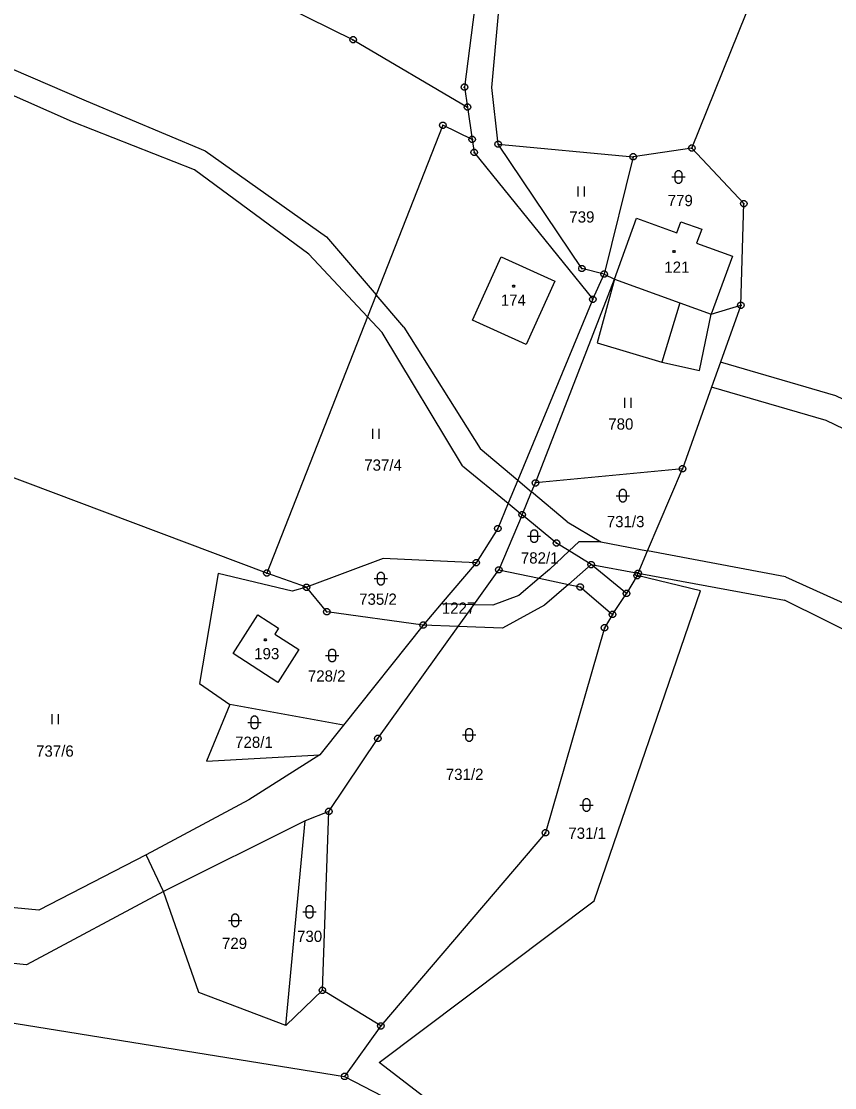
# Model space of a CAD drawing. Extents: x -694465 to -690527, y -983694 to -978978.
# Drawn here: x -690934.9 to -690812.1, y -980605.1 to -980444.1 of the extents above; entities that cross this region are included whole.
import ezdxf

# ---------------------------------------------------------------- set-up
doc = ezdxf.new("R2010")
doc.units = 0
for name, color, linetype in [('Vrstva 1', 7, 'Continuous'), ('Vrstva 18', 7, 'Continuous'), ('Vrstva 19', 7, 'Continuous'), ('Vrstva 24', 7, 'Continuous'), ('Vrstva 25', 7, 'Continuous')]:
    doc.layers.add(name, color=color, linetype=linetype)

msp = doc.modelspace()

# ---------------------------------------------------------------- linework, layer by layer
at = {"layer": 'Vrstva 1'}
for points in [[(-690865.21, -980431.98), (-690868.03, -980454.02)], [(-690863.87, -980454.07), (-690861.93, -980432.34)], [(-690895.13, -980441.8), (-690884.84, -980446.86)], [(-690833.66, -980463.22), (-690825.488, -980442.912)], [(-690884.84, -980446.86), (-690867.57, -980457.03)], [(-690936.46, -980451.23), (-690925.16, -980456.08)], [(-690927.2, -980459.26), (-690937.78, -980454.57)], [(-690868.03, -980454.02), (-690867.57, -980457.03)], [(-690862.93, -980462.64), (-690863.87, -980454.07)], [(-690925.16, -980456.08), (-690907.17, -980463.65)], [(-690867.57, -980457.03), (-690866.84, -980461.91)], [(-690908.81, -980466.51), (-690927.2, -980459.26)], [(-690871.29, -980459.78), (-690881.35, -980485.41)], [(-690866.84, -980461.91), (-690871.29, -980459.78)], [(-690866.84, -980461.91), (-690866.54, -980463.88)], [(-690907.17, -980463.65), (-690888.85, -980476.65)], [(-690850.27, -980481.42), (-690862.93, -980462.64)], [(-690862.93, -980462.64), (-690842.56, -980464.55)], [(-690833.66, -980463.22), (-690842.56, -980464.55)], [(-690825.84, -980471.62), (-690833.66, -980463.22)], [(-690866.54, -980463.88), (-690848.65, -980486.07)], [(-690842.56, -980464.55), (-690846.92, -980482.26)], [(-690891.52, -980479.26), (-690908.81, -980466.51)], [(-690826.26, -980486.97), (-690825.84, -980471.62)], [(-690845.37, -980483.01), (-690842.02, -980473.81)], [(-690842.02, -980473.81), (-690835.94, -980476.02)], [(-690835.94, -980476.02), (-690835.33, -980474.36)], [(-690835.33, -980474.36), (-690832.19, -980475.5)], [(-690832.19, -980475.5), (-690832.95, -980477.6)], [(-690888.85, -980476.65), (-690881.35, -980485.41)], [(-690832.95, -980477.6), (-690827.55, -980479.57)], [(-690891.52, -980479.26), (-690882.65, -980488.72)], [(-690854.36, -980483.34), (-690858.69, -980492.92), (-690866.82, -980489.24), (-690862.49, -980479.67), (-690854.36, -980483.34)], [(-690827.55, -980479.57), (-690830.75, -980488.34)], [(-690846.92, -980482.26), (-690850.27, -980481.42)], [(-690848.65, -980486.07), (-690846.92, -980482.26)], [(-690846.92, -980482.26), (-690845.37, -980483.01)], [(-690857.3, -980513.8), (-690845.37, -980483.01)], [(-690845.37, -980483.01), (-690847.98, -980492.63)], [(-690845.37, -980483.01), (-690835.5, -980486.6)], [(-690881.35, -980485.41), (-690882.65, -980488.72)], [(-690877.17, -980490.3), (-690881.35, -980485.41)], [(-690848.65, -980486.07), (-690859.95, -980513.39)], [(-690835.5, -980486.6), (-690838.2, -980495.55)], [(-690835.5, -980486.6), (-690830.75, -980488.34)], [(-690830.75, -980488.34), (-690826.26, -980486.97)], [(-690826.26, -980486.97), (-690829.339, -980495.559)], [(-690882.65, -980488.72), (-690897.85, -980527.41)], [(-690880.46, -980491.06), (-690882.65, -980488.72)], [(-690832.54, -980496.81), (-690830.75, -980488.34)], [(-690877.17, -980490.3), (-690865.63, -980508.59)], [(-690868.3, -980511.2), (-690880.46, -980491.06)], [(-690847.98, -980492.63), (-690838.2, -980495.55)], [(-690838.2, -980495.55), (-690832.54, -980496.81)], [(-690829.339, -980495.559), (-690830.692, -980499.335)], [(-690686.191, -980555.869), (-690699.761, -980553.812), (-690734.587, -980544.354), (-690762.898, -980529.445), (-690786.026, -980513.096), (-690811.934, -980500.644), (-690829.339, -980495.559)], [(-690830.692, -980499.335), (-690835.11, -980511.66)], [(-690700.76, -980557.694), (-690736.061, -980548.098), (-690764.994, -980532.863), (-690788.062, -980516.556), (-690813.374, -980504.39), (-690830.692, -980499.335)], [(-690865.63, -980508.59), (-690859.95, -980513.39)], [(-690868.3, -980511.2), (-690861.4, -980516.88)], [(-690835.11, -980511.66), (-690857.3, -980513.8)], [(-690840.35, -980524.05), (-690835.11, -980511.66)], [(-690897.85, -980527.41), (-690938.29, -980512.22)], [(-690859.95, -980513.39), (-690861.4, -980516.88)], [(-690859.95, -980513.39), (-690857.87, -980515.15)], [(-690859.31, -980518.6), (-690857.87, -980515.15)], [(-690857.87, -980515.15), (-690857.3, -980513.8)], [(-690852.49, -980519.7), (-690857.87, -980515.15)], [(-690861.4, -980516.88), (-690862.98, -980520.69)], [(-690861.4, -980516.88), (-690859.31, -980518.6)], [(-690859.31, -980518.6), (-690862.81, -980526.93)], [(-690854.12, -980522.88), (-690859.31, -980518.6)], [(-690852.49, -980519.7), (-690847.4, -980522.71)], [(-690862.98, -980520.69), (-690866.24, -980525.85)], [(-690852.194, -980524.078), (-690854.12, -980522.88)], [(-690847.4, -980522.71), (-690850.763, -980522.725), (-690852.194, -980524.078)], [(-690847.4, -980522.71), (-690840.35, -980524.05)], [(-690852.194, -980524.078), (-690855.173, -980526.893), (-690856.732, -980528.207)], [(-690848.88, -980526.14), (-690852.194, -980524.078)], [(-690841.79, -980527.44), (-690840.35, -980524.05)], [(-690819.55, -980527.99), (-690840.35, -980524.05)], [(-690880.31, -980525.21), (-690891.88, -980529.56)], [(-690866.24, -980525.85), (-690880.31, -980525.21)], [(-690866.24, -980525.85), (-690871.555, -980532.091)], [(-690848.88, -980526.14), (-690852.307, -980529.137)], [(-690843.56, -980530.49), (-690848.88, -980526.14)], [(-690848.88, -980526.14), (-690841.79, -980527.44)], [(-690905.21, -980527.48), (-690908.04, -980544.08)], [(-690894.04, -980530.17), (-690905.21, -980527.48)], [(-690891.88, -980529.56), (-690897.85, -980527.41)], [(-690866.609, -980532.215), (-690862.81, -980526.93)], [(-690862.81, -980526.93), (-690856.732, -980528.207)], [(-690841.94, -980527.81), (-690843.56, -980530.49)], [(-690841.94, -980527.81), (-690841.79, -980527.44)], [(-690832.37, -980530.09), (-690841.94, -980527.81)], [(-690841.79, -980527.44), (-690819.67, -980531.51)], [(-690819.55, -980527.99), (-690799.34, -980537.1)], [(-690891.88, -980529.56), (-690894.04, -980530.17)], [(-690888.8, -980533.27), (-690891.88, -980529.56)], [(-690852.307, -980529.137), (-690855.909, -980532.287), (-690862.28, -980535.719), (-690868.952, -980535.475)], [(-690856.732, -980528.207), (-690859.829, -980530.816), (-690863.75, -980532.287), (-690866.609, -980532.215)], [(-690856.732, -980528.207), (-690852.307, -980529.137)], [(-690852.307, -980529.137), (-690850.53, -980529.51)], [(-690850.53, -980529.51), (-690845.65, -980533.66)], [(-690848.44, -980576.92), (-690832.37, -980530.09)], [(-690845.65, -980533.66), (-690843.56, -980530.49)], [(-690871.555, -980532.091), (-690874.27, -980535.28)], [(-690866.609, -980532.215), (-690871.555, -980532.091)], [(-690868.952, -980535.475), (-690866.609, -980532.215)], [(-690801.3, -980540.6), (-690819.67, -980531.51)], [(-690893.02, -980538.98), (-690896.22, -980543.93), (-690902.96, -980539.57), (-690899.2, -980533.73), (-690896.1, -980535.73), (-690896.67, -980536.63), (-690893.02, -980538.98)], [(-690874.27, -980535.28), (-690888.8, -980533.27)], [(-690845.65, -980533.66), (-690846.85, -980535.68)], [(-690874.27, -980535.28), (-690886.28, -980550.41)], [(-690881.11, -980552.39), (-690868.952, -980535.475)], [(-690868.952, -980535.475), (-690874.27, -980535.28)], [(-690846.85, -980535.68), (-690855.8, -980566.65)], [(-690908.04, -980544.08), (-690903.44, -980547.26)], [(-690903.44, -980547.26), (-690906.98, -980555.85)], [(-690886.28, -980550.41), (-690903.44, -980547.26)], [(-690886.28, -980550.41), (-690889.85, -980554.85)], [(-690888.52, -980563.42), (-690881.11, -980552.39)], [(-690906.98, -980555.85), (-690889.85, -980554.85)], [(-690889.85, -980554.85), (-690900.57, -980561.68)], [(-690900.57, -980561.68), (-690916.11, -980569.98)], [(-690888.52, -980563.42), (-690892.05, -980564.82)], [(-690889.48, -980590.44), (-690888.52, -980563.42)], [(-690892.05, -980564.82), (-690913.45, -980575.53)], [(-690894.98, -980595.74), (-690892.05, -980564.82)], [(-690855.8, -980566.65), (-690880.66, -980595.82)], [(-690916.11, -980569.98), (-690932.28, -980578.35)], [(-690913.45, -980575.53), (-690916.11, -980569.98)], [(-690932.28, -980578.35), (-690960.27, -980575.64)], [(-690913.45, -980575.53), (-690934.14, -980586.57)], [(-690908.12, -980590.79), (-690913.45, -980575.53)], [(-690880.89, -980601.34), (-690848.44, -980576.92)], [(-690934.14, -980586.57), (-691001.09, -980579.72)], [(-691001.55, -980584.83), (-690886.11, -980603.44)], [(-690894.98, -980595.74), (-690908.12, -980590.79)], [(-690889.48, -980590.44), (-690894.98, -980595.74)], [(-690880.66, -980595.82), (-690889.48, -980590.44)], [(-690880.66, -980595.82), (-690886.11, -980603.44)], [(-690861.7, -980616.11), (-690880.89, -980601.34)], [(-690886.11, -980603.44), (-690861.7, -980616.11)]]:
    msp.add_lwpolyline(points, dxfattribs=at)
at = {"layer": 'Vrstva 24'}
for points in [[(-690884.686, -980446.384), (-690884.436, -980446.566), (-690884.34, -980446.86), (-690884.436, -980447.154), (-690884.686, -980447.336), (-690884.994, -980447.336), (-690885.244, -980447.154), (-690885.34, -980446.86), (-690885.244, -980446.566), (-690884.994, -980446.384)], [(-690867.876, -980453.544), (-690867.626, -980453.726), (-690867.53, -980454.02), (-690867.626, -980454.314), (-690867.876, -980454.496), (-690868.184, -980454.496), (-690868.434, -980454.314), (-690868.53, -980454.02), (-690868.434, -980453.726), (-690868.184, -980453.544)], [(-690867.416, -980456.554), (-690867.166, -980456.736), (-690867.07, -980457.03), (-690867.166, -980457.324), (-690867.416, -980457.506), (-690867.724, -980457.506), (-690867.974, -980457.324), (-690868.07, -980457.03), (-690867.974, -980456.736), (-690867.724, -980456.554)], [(-690871.136, -980459.304), (-690870.886, -980459.486), (-690870.79, -980459.78), (-690870.886, -980460.074), (-690871.136, -980460.256), (-690871.444, -980460.256), (-690871.694, -980460.074), (-690871.79, -980459.78), (-690871.694, -980459.486), (-690871.444, -980459.304)], [(-690866.686, -980461.434), (-690866.436, -980461.616), (-690866.34, -980461.91), (-690866.436, -980462.204), (-690866.686, -980462.386), (-690866.994, -980462.386), (-690867.244, -980462.204), (-690867.34, -980461.91), (-690867.244, -980461.616), (-690866.994, -980461.434)], [(-690866.386, -980463.404), (-690866.136, -980463.586), (-690866.04, -980463.88), (-690866.136, -980464.174), (-690866.386, -980464.356), (-690866.694, -980464.356), (-690866.944, -980464.174), (-690867.04, -980463.88), (-690866.944, -980463.586), (-690866.694, -980463.404)], [(-690862.776, -980462.164), (-690862.526, -980462.346), (-690862.43, -980462.64), (-690862.526, -980462.934), (-690862.776, -980463.116), (-690863.084, -980463.116), (-690863.334, -980462.934), (-690863.43, -980462.64), (-690863.334, -980462.346), (-690863.084, -980462.164)], [(-690833.506, -980462.744), (-690833.256, -980462.926), (-690833.16, -980463.22), (-690833.256, -980463.514), (-690833.506, -980463.696), (-690833.814, -980463.696), (-690834.064, -980463.514), (-690834.16, -980463.22), (-690834.064, -980462.926), (-690833.814, -980462.744)], [(-690842.406, -980464.074), (-690842.156, -980464.256), (-690842.06, -980464.55), (-690842.156, -980464.844), (-690842.406, -980465.026), (-690842.714, -980465.026), (-690842.964, -980464.844), (-690843.06, -980464.55), (-690842.964, -980464.256), (-690842.714, -980464.074)], [(-690825.686, -980471.144), (-690825.436, -980471.326), (-690825.34, -980471.62), (-690825.436, -980471.914), (-690825.686, -980472.096), (-690825.994, -980472.096), (-690826.244, -980471.914), (-690826.34, -980471.62), (-690826.244, -980471.326), (-690825.994, -980471.144)], [(-690850.116, -980480.944), (-690849.866, -980481.126), (-690849.77, -980481.42), (-690849.866, -980481.714), (-690850.116, -980481.896), (-690850.424, -980481.896), (-690850.674, -980481.714), (-690850.77, -980481.42), (-690850.674, -980481.126), (-690850.424, -980480.944)], [(-690846.766, -980481.784), (-690846.516, -980481.966), (-690846.42, -980482.26), (-690846.516, -980482.554), (-690846.766, -980482.736), (-690847.074, -980482.736), (-690847.324, -980482.554), (-690847.42, -980482.26), (-690847.324, -980481.966), (-690847.074, -980481.784)], [(-690848.496, -980485.594), (-690848.246, -980485.776), (-690848.15, -980486.07), (-690848.246, -980486.364), (-690848.496, -980486.546), (-690848.804, -980486.546), (-690849.054, -980486.364), (-690849.15, -980486.07), (-690849.054, -980485.776), (-690848.804, -980485.594)], [(-690826.106, -980486.494), (-690825.856, -980486.676), (-690825.76, -980486.97), (-690825.856, -980487.264), (-690826.106, -980487.446), (-690826.414, -980487.446), (-690826.664, -980487.264), (-690826.76, -980486.97), (-690826.664, -980486.676), (-690826.414, -980486.494)], [(-690834.956, -980511.184), (-690834.706, -980511.366), (-690834.61, -980511.66), (-690834.706, -980511.954), (-690834.956, -980512.136), (-690835.264, -980512.136), (-690835.514, -980511.954), (-690835.61, -980511.66), (-690835.514, -980511.366), (-690835.264, -980511.184)], [(-690857.146, -980513.324), (-690856.896, -980513.506), (-690856.8, -980513.8), (-690856.896, -980514.094), (-690857.146, -980514.276), (-690857.454, -980514.276), (-690857.704, -980514.094), (-690857.8, -980513.8), (-690857.704, -980513.506), (-690857.454, -980513.324)], [(-690859.156, -980518.124), (-690858.906, -980518.306), (-690858.81, -980518.6), (-690858.906, -980518.894), (-690859.156, -980519.076), (-690859.464, -980519.076), (-690859.714, -980518.894), (-690859.81, -980518.6), (-690859.714, -980518.306), (-690859.464, -980518.124)], [(-690862.826, -980520.214), (-690862.576, -980520.396), (-690862.48, -980520.69), (-690862.576, -980520.984), (-690862.826, -980521.166), (-690863.134, -980521.166), (-690863.384, -980520.984), (-690863.48, -980520.69), (-690863.384, -980520.396), (-690863.134, -980520.214)], [(-690853.966, -980522.404), (-690853.716, -980522.586), (-690853.62, -980522.88), (-690853.716, -980523.174), (-690853.966, -980523.356), (-690854.274, -980523.356), (-690854.524, -980523.174), (-690854.62, -980522.88), (-690854.524, -980522.586), (-690854.274, -980522.404)], [(-690866.086, -980525.374), (-690865.836, -980525.556), (-690865.74, -980525.85), (-690865.836, -980526.144), (-690866.086, -980526.326), (-690866.394, -980526.326), (-690866.644, -980526.144), (-690866.74, -980525.85), (-690866.644, -980525.556), (-690866.394, -980525.374)], [(-690862.656, -980526.454), (-690862.406, -980526.636), (-690862.31, -980526.93), (-690862.406, -980527.224), (-690862.656, -980527.406), (-690862.964, -980527.406), (-690863.214, -980527.224), (-690863.31, -980526.93), (-690863.214, -980526.636), (-690862.964, -980526.454)], [(-690848.726, -980525.664), (-690848.476, -980525.846), (-690848.38, -980526.14), (-690848.476, -980526.434), (-690848.726, -980526.616), (-690849.034, -980526.616), (-690849.284, -980526.434), (-690849.38, -980526.14), (-690849.284, -980525.846), (-690849.034, -980525.664)], [(-690897.696, -980526.934), (-690897.446, -980527.116), (-690897.35, -980527.41), (-690897.446, -980527.704), (-690897.696, -980527.886), (-690898.004, -980527.886), (-690898.254, -980527.704), (-690898.35, -980527.41), (-690898.254, -980527.116), (-690898.004, -980526.934)], [(-690841.786, -980527.334), (-690841.536, -980527.516), (-690841.44, -980527.81), (-690841.536, -980528.104), (-690841.786, -980528.286), (-690842.094, -980528.286), (-690842.344, -980528.104), (-690842.44, -980527.81), (-690842.344, -980527.516), (-690842.094, -980527.334)], [(-690841.636, -980526.964), (-690841.386, -980527.146), (-690841.29, -980527.44), (-690841.386, -980527.734), (-690841.636, -980527.916), (-690841.944, -980527.916), (-690842.194, -980527.734), (-690842.29, -980527.44), (-690842.194, -980527.146), (-690841.944, -980526.964)], [(-690891.726, -980529.084), (-690891.476, -980529.266), (-690891.38, -980529.56), (-690891.476, -980529.854), (-690891.726, -980530.036), (-690892.034, -980530.036), (-690892.284, -980529.854), (-690892.38, -980529.56), (-690892.284, -980529.266), (-690892.034, -980529.084)], [(-690850.376, -980529.034), (-690850.126, -980529.216), (-690850.03, -980529.51), (-690850.126, -980529.804), (-690850.376, -980529.986), (-690850.684, -980529.986), (-690850.934, -980529.804), (-690851.03, -980529.51), (-690850.934, -980529.216), (-690850.684, -980529.034)], [(-690843.406, -980530.014), (-690843.156, -980530.196), (-690843.06, -980530.49), (-690843.156, -980530.784), (-690843.406, -980530.966), (-690843.714, -980530.966), (-690843.964, -980530.784), (-690844.06, -980530.49), (-690843.964, -980530.196), (-690843.714, -980530.014)], [(-690888.646, -980532.794), (-690888.396, -980532.976), (-690888.3, -980533.27), (-690888.396, -980533.564), (-690888.646, -980533.746), (-690888.954, -980533.746), (-690889.204, -980533.564), (-690889.3, -980533.27), (-690889.204, -980532.976), (-690888.954, -980532.794)], [(-690845.496, -980533.184), (-690845.246, -980533.366), (-690845.15, -980533.66), (-690845.246, -980533.954), (-690845.496, -980534.136), (-690845.804, -980534.136), (-690846.054, -980533.954), (-690846.15, -980533.66), (-690846.054, -980533.366), (-690845.804, -980533.184)], [(-690874.116, -980534.804), (-690873.866, -980534.986), (-690873.77, -980535.28), (-690873.866, -980535.574), (-690874.116, -980535.756), (-690874.424, -980535.756), (-690874.674, -980535.574), (-690874.77, -980535.28), (-690874.674, -980534.986), (-690874.424, -980534.804)], [(-690846.696, -980535.204), (-690846.446, -980535.386), (-690846.35, -980535.68), (-690846.446, -980535.974), (-690846.696, -980536.156), (-690847.004, -980536.156), (-690847.254, -980535.974), (-690847.35, -980535.68), (-690847.254, -980535.386), (-690847.004, -980535.204)], [(-690880.956, -980551.914), (-690880.706, -980552.096), (-690880.61, -980552.39), (-690880.706, -980552.684), (-690880.956, -980552.866), (-690881.264, -980552.866), (-690881.514, -980552.684), (-690881.61, -980552.39), (-690881.514, -980552.096), (-690881.264, -980551.914)], [(-690888.366, -980562.944), (-690888.116, -980563.126), (-690888.02, -980563.42), (-690888.116, -980563.714), (-690888.366, -980563.896), (-690888.674, -980563.896), (-690888.924, -980563.714), (-690889.02, -980563.42), (-690888.924, -980563.126), (-690888.674, -980562.944)], [(-690855.646, -980566.174), (-690855.396, -980566.356), (-690855.3, -980566.65), (-690855.396, -980566.944), (-690855.646, -980567.126), (-690855.954, -980567.126), (-690856.204, -980566.944), (-690856.3, -980566.65), (-690856.204, -980566.356), (-690855.954, -980566.174)], [(-690889.326, -980589.964), (-690889.076, -980590.146), (-690888.98, -980590.44), (-690889.076, -980590.734), (-690889.326, -980590.916), (-690889.634, -980590.916), (-690889.884, -980590.734), (-690889.98, -980590.44), (-690889.884, -980590.146), (-690889.634, -980589.964)], [(-690880.506, -980595.344), (-690880.256, -980595.526), (-690880.16, -980595.82), (-690880.256, -980596.114), (-690880.506, -980596.296), (-690880.814, -980596.296), (-690881.064, -980596.114), (-690881.16, -980595.82), (-690881.064, -980595.526), (-690880.814, -980595.344)], [(-690885.956, -980602.964), (-690885.706, -980603.146), (-690885.61, -980603.44), (-690885.706, -980603.734), (-690885.956, -980603.916), (-690886.264, -980603.916), (-690886.514, -980603.734), (-690886.61, -980603.44), (-690886.514, -980603.146), (-690886.264, -980602.964)]]:
    msp.add_lwpolyline(points, close=True, dxfattribs=at)
for points in [[(-690884.959, -980446.86), (-690884.72, -980446.86)], [(-690868.149, -980454.02), (-690867.91, -980454.02)], [(-690867.689, -980457.03), (-690867.45, -980457.03)], [(-690871.409, -980459.78), (-690871.17, -980459.78)], [(-690866.959, -980461.91), (-690866.72, -980461.91)], [(-690863.049, -980462.64), (-690862.81, -980462.64)], [(-690833.779, -980463.22), (-690833.54, -980463.22)], [(-690866.659, -980463.88), (-690866.42, -980463.88)], [(-690842.679, -980464.55), (-690842.44, -980464.55)], [(-690825.959, -980471.62), (-690825.72, -980471.62)], [(-690850.389, -980481.42), (-690850.15, -980481.42)], [(-690847.039, -980482.26), (-690846.8, -980482.26)], [(-690848.769, -980486.07), (-690848.53, -980486.07)], [(-690826.379, -980486.97), (-690826.14, -980486.97)], [(-690835.229, -980511.66), (-690834.99, -980511.66)], [(-690857.419, -980513.8), (-690857.18, -980513.8)], [(-690859.429, -980518.6), (-690859.19, -980518.6)], [(-690863.099, -980520.69), (-690862.86, -980520.69)], [(-690854.239, -980522.88), (-690854, -980522.88)], [(-690866.359, -980525.85), (-690866.12, -980525.85)], [(-690848.999, -980526.14), (-690848.76, -980526.14)], [(-690897.969, -980527.41), (-690897.73, -980527.41)], [(-690862.929, -980526.93), (-690862.69, -980526.93)], [(-690842.059, -980527.81), (-690841.82, -980527.81)], [(-690841.909, -980527.44), (-690841.67, -980527.44)], [(-690891.999, -980529.56), (-690891.76, -980529.56)], [(-690850.649, -980529.51), (-690850.41, -980529.51)], [(-690843.679, -980530.49), (-690843.44, -980530.49)], [(-690888.919, -980533.27), (-690888.68, -980533.27)], [(-690845.769, -980533.66), (-690845.53, -980533.66)], [(-690874.389, -980535.28), (-690874.15, -980535.28)], [(-690846.969, -980535.68), (-690846.73, -980535.68)], [(-690881.229, -980552.39), (-690880.99, -980552.39)], [(-690888.639, -980563.42), (-690888.4, -980563.42)], [(-690855.919, -980566.65), (-690855.68, -980566.65)], [(-690889.599, -980590.44), (-690889.36, -980590.44)], [(-690880.779, -980595.82), (-690880.54, -980595.82)], [(-690886.229, -980603.44), (-690885.99, -980603.44)]]:
    msp.add_lwpolyline(points, dxfattribs=at)
at = {"layer": 'Vrstva 25'}
for points in [[(-690836.18, -980467.09), (-690836.085, -980466.796), (-690835.835, -980466.614), (-690835.525, -980466.614), (-690835.275, -980466.796), (-690835.18, -980467.09), (-690835.18, -980468.09), (-690835.275, -980468.384), (-690835.525, -980468.566), (-690835.835, -980468.566), (-690836.085, -980468.384), (-690836.18, -980468.09)], [(-690836.293, -980478.708), (-690836.205, -980478.86), (-690836.293, -980479.012), (-690836.467, -980479.012), (-690836.555, -980478.86), (-690836.467, -980478.708)], [(-690860.503, -980483.938), (-690860.415, -980484.09), (-690860.503, -980484.242), (-690860.677, -980484.242), (-690860.765, -980484.09), (-690860.677, -980483.938)], [(-690844.61, -980515.23), (-690844.515, -980514.936), (-690844.265, -980514.754), (-690843.955, -980514.754), (-690843.705, -980514.936), (-690843.61, -980515.23), (-690843.61, -980516.23), (-690843.705, -980516.524), (-690843.955, -980516.706), (-690844.265, -980516.706), (-690844.515, -980516.524), (-690844.61, -980516.23)], [(-690858.01, -980521.35), (-690857.915, -980521.056), (-690857.665, -980520.874), (-690857.355, -980520.874), (-690857.105, -980521.056), (-690857.01, -980521.35), (-690857.01, -980522.35), (-690857.105, -980522.644), (-690857.355, -980522.826), (-690857.665, -980522.826), (-690857.915, -980522.644), (-690858.01, -980522.35)], [(-690881.14, -980527.76), (-690881.045, -980527.466), (-690880.795, -980527.284), (-690880.485, -980527.284), (-690880.235, -980527.466), (-690880.14, -980527.76), (-690880.14, -980528.76), (-690880.235, -980529.054), (-690880.485, -980529.236), (-690880.795, -980529.236), (-690881.045, -980529.054), (-690881.14, -980528.76)], [(-690897.993, -980537.328), (-690897.905, -980537.48), (-690897.993, -980537.632), (-690898.167, -980537.632), (-690898.255, -980537.48), (-690898.167, -980537.328)], [(-690888.5, -980539.37), (-690888.405, -980539.076), (-690888.155, -980538.894), (-690887.845, -980538.894), (-690887.595, -980539.076), (-690887.5, -980539.37), (-690887.5, -980540.37), (-690887.595, -980540.664), (-690887.845, -980540.846), (-690888.155, -980540.846), (-690888.405, -980540.664), (-690888.5, -980540.37)], [(-690900.21, -980549.48), (-690900.115, -980549.186), (-690899.865, -980549.004), (-690899.555, -980549.004), (-690899.305, -980549.186), (-690899.21, -980549.48), (-690899.21, -980550.48), (-690899.305, -980550.774), (-690899.555, -980550.956), (-690899.865, -980550.956), (-690900.115, -980550.774), (-690900.21, -980550.48)], [(-690867.81, -980551.36), (-690867.715, -980551.066), (-690867.465, -980550.884), (-690867.155, -980550.884), (-690866.905, -980551.066), (-690866.81, -980551.36), (-690866.81, -980552.36), (-690866.905, -980552.654), (-690867.155, -980552.836), (-690867.465, -980552.836), (-690867.715, -980552.654), (-690867.81, -980552.36)], [(-690850.09, -980561.95), (-690849.995, -980561.656), (-690849.745, -980561.474), (-690849.435, -980561.474), (-690849.185, -980561.656), (-690849.09, -980561.95), (-690849.09, -980562.95), (-690849.185, -980563.244), (-690849.435, -980563.426), (-690849.745, -980563.426), (-690849.995, -980563.244), (-690850.09, -980562.95)], [(-690891.93, -980578.08), (-690891.835, -980577.786), (-690891.585, -980577.604), (-690891.275, -980577.604), (-690891.025, -980577.786), (-690890.93, -980578.08), (-690890.93, -980579.08), (-690891.025, -980579.374), (-690891.275, -980579.556), (-690891.585, -980579.556), (-690891.835, -980579.374), (-690891.93, -980579.08)], [(-690903.15, -980579.38), (-690903.055, -980579.086), (-690902.805, -980578.904), (-690902.495, -980578.904), (-690902.245, -980579.086), (-690902.15, -980579.38), (-690902.15, -980580.38), (-690902.245, -980580.674), (-690902.495, -980580.856), (-690902.805, -980580.856), (-690903.055, -980580.674), (-690903.15, -980580.38)]]:
    msp.add_lwpolyline(points, close=True, dxfattribs=at)
for points in [[(-690836.68, -980467.59), (-690834.68, -980467.59)], [(-690850.91, -980469.03), (-690850.91, -980470.53)], [(-690849.91, -980470.53), (-690849.91, -980469.03)], [(-690843.85, -980500.94), (-690843.85, -980502.44)], [(-690842.85, -980502.44), (-690842.85, -980500.94)], [(-690881.9, -980505.62), (-690881.9, -980507.12)], [(-690880.9, -980507.12), (-690880.9, -980505.62)], [(-690845.11, -980515.73), (-690843.11, -980515.73)], [(-690858.51, -980521.85), (-690856.51, -980521.85)], [(-690881.64, -980528.26), (-690879.64, -980528.26)], [(-690889, -980539.87), (-690887, -980539.87)], [(-690930.34, -980548.72), (-690930.34, -980550.22)], [(-690929.34, -980550.22), (-690929.34, -980548.72)], [(-690900.71, -980549.98), (-690898.71, -980549.98)], [(-690868.31, -980551.86), (-690866.31, -980551.86)], [(-690850.59, -980562.45), (-690848.59, -980562.45)], [(-690892.43, -980578.58), (-690890.43, -980578.58)], [(-690903.65, -980579.88), (-690901.65, -980579.88)]]:
    msp.add_lwpolyline(points, dxfattribs=at)

# ---------------------------------------------------------------- texts
at = {"layer": 'Vrstva 18'}
for s, p in [('779', (-690837.324, -980472)), ('739', (-690852.181, -980474.48)), ('780', (-690846.297, -980505.76)), ('737/4', (-690883.153, -980511.96)), ('731/3', (-690846.523, -980520.49)), ('782/1', (-690859.503, -980525.98)), ('735/2', (-690883.921, -980532.21)), ('1227', (-690871.433, -980533.56)), ('728/2', (-690891.667, -980543.81)), ('728/1', (-690902.655, -980553.82)), ('737/6', (-690932.713, -980555.15)), ('731/2', (-690870.833, -980558.67)), ('731/1', (-690852.333, -980567.56)), ('729', (-690904.638, -980584.19)), ('730', (-690893.298, -980583.13))]:
    msp.add_text(s, height=1.7, dxfattribs=at).set_placement(p)
at = {"layer": 'Vrstva 19'}
for s, p in [('121', (-690837.832, -980482.07)), ('174', (-690862.526, -980487.05)), ('193', (-690899.773, -980540.44))]:
    msp.add_text(s, height=1.7, dxfattribs=at).set_placement(p)

doc.saveas('drawing.dxf')
